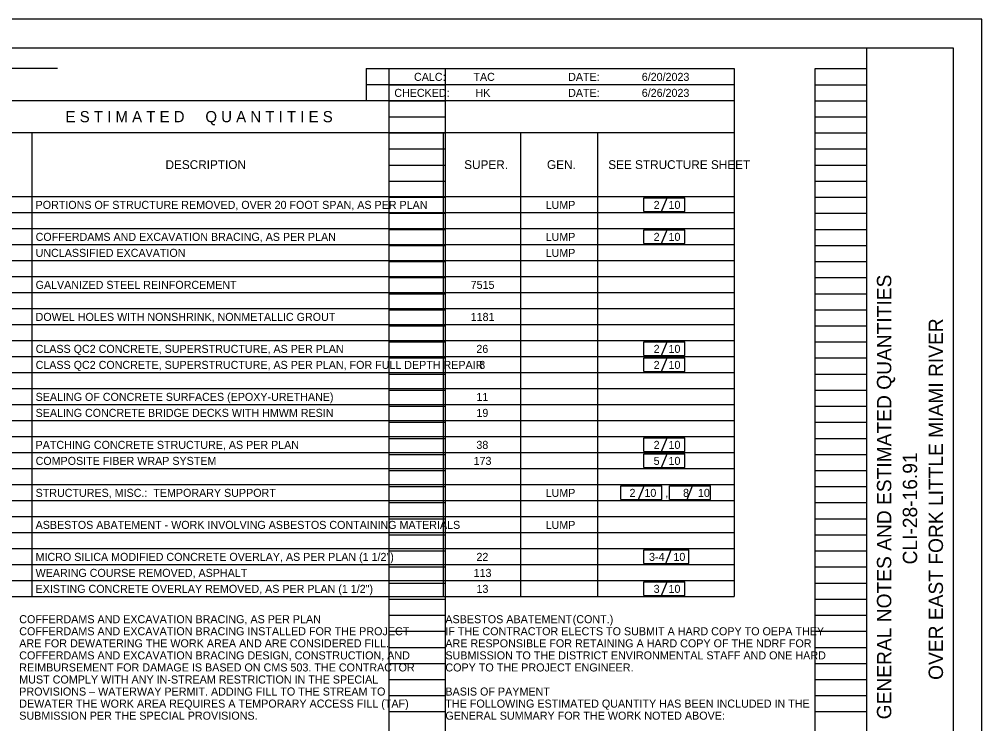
# Model space of a CAD drawing. Extents: x 0 to 34, y 0 to 22.
# Drawn here: x 17.24 to 34, y 9.73 to 22 of the extents above; entities that cross this region are included whole.
import ezdxf

# ---------------------------------------------------------------- set-up
doc = ezdxf.new("R2010")
doc.units = 0
for name, color, linetype in [('BR_P_Gen_Text', 7, 'Continuous'), ('SC_Scratch5', 7, 'Continuous'), ('SH_Border', 7, 'Continuous'), ('SH_Cut_Line', 7, 'Continuous'), ('SH_Data', 7, 'Continuous'), ('SH_Masking', 7, 'Continuous'), ('SH_Text', 7, 'Continuous')]:
    doc.layers.add(name, color=color, linetype=linetype)

msp = doc.modelspace()

# ---------------------------------------------------------------- linework, layer by layer
at = {"layer": 'BR_P_Gen_Text'}
for p, q in [((28.117, 18.888), (28.83, 18.888)), ((28.117, 18.651), (28.117, 18.888)), ((28.426, 18.651), (28.521, 18.888)), ((28.83, 18.651), (28.83, 18.888)), ((28.117, 18.651), (28.83, 18.651)), ((28.117, 18.331), (28.83, 18.331)), ((28.117, 18.093), (28.117, 18.331)), ((28.426, 18.093), (28.521, 18.331)), ((28.83, 18.093), (28.83, 18.331)), ((28.117, 18.093), (28.83, 18.093)), ((28.117, 16.38), (28.83, 16.38)), ((28.117, 16.142), (28.117, 16.38)), ((28.426, 16.142), (28.521, 16.38)), ((28.83, 16.142), (28.83, 16.38)), ((28.117, 16.142), (28.83, 16.142)), ((28.117, 16.101), (28.83, 16.101)), ((28.117, 15.864), (28.117, 16.101)), ((28.426, 15.864), (28.521, 16.101)), ((28.83, 15.864), (28.83, 16.101)), ((28.117, 15.864), (28.83, 15.864)), ((28.117, 14.708), (28.83, 14.708)), ((28.117, 14.47), (28.117, 14.708)), ((28.426, 14.47), (28.521, 14.708)), ((28.83, 14.47), (28.83, 14.708)), ((28.117, 14.47), (28.83, 14.47)), ((28.117, 14.429), (28.83, 14.429)), ((28.117, 14.192), (28.117, 14.429)), ((28.426, 14.192), (28.521, 14.429)), ((28.83, 14.192), (28.83, 14.429)), ((28.117, 14.192), (28.83, 14.192)), ((27.715, 13.872), (28.427, 13.872)), ((27.715, 13.634), (27.715, 13.872)), ((28.024, 13.634), (28.119, 13.872)), ((28.427, 13.634), (28.427, 13.872)), ((28.562, 13.872), (29.274, 13.872)), ((28.562, 13.634), (28.562, 13.872)), ((28.871, 13.634), (28.966, 13.872)), ((29.274, 13.634), (29.274, 13.872)), ((27.715, 13.634), (28.427, 13.634)), ((28.562, 13.634), (29.274, 13.634)), ((28.117, 12.757), (28.901, 12.757)), ((28.117, 12.519), (28.117, 12.757)), ((28.498, 12.519), (28.593, 12.757)), ((28.901, 12.519), (28.901, 12.757)), ((28.117, 12.519), (28.901, 12.519)), ((28.117, 12.199), (28.83, 12.199)), ((28.117, 11.962), (28.117, 12.199)), ((28.426, 11.962), (28.521, 12.199)), ((28.83, 11.962), (28.83, 12.199)), ((28.117, 11.962), (28.83, 11.962))]:
    msp.add_line(p, q, dxfattribs=at)
at = {"layer": 'SC_Scratch5'}
for p, q in [((23.68, 0.98), (23.68, 21.14)), ((23.68, 21.14), (24.66, 21.14)), ((24.66, 0.98), (24.66, 21.14)), ((31.1, 0.98), (31.1, 21.14)), ((31.1, 21.14), (32, 21.14)), ((32, 0.98), (32, 21.14)), ((23.68, 20.86), (24.66, 20.86)), ((31.1, 20.86), (32, 20.86)), ((23.68, 20.58), (24.66, 20.58)), ((31.1, 20.58), (32, 20.58)), ((23.68, 20.3), (24.66, 20.3)), ((31.1, 20.3), (32, 20.3)), ((23.68, 20.02), (24.66, 20.02)), ((31.1, 20.02), (32, 20.02)), ((23.68, 19.74), (24.66, 19.74)), ((31.1, 19.74), (32, 19.74)), ((23.68, 19.46), (24.66, 19.46)), ((31.1, 19.46), (32, 19.46)), ((23.68, 19.18), (24.66, 19.18)), ((31.1, 19.18), (32, 19.18)), ((23.68, 18.9), (24.66, 18.9)), ((31.1, 18.9), (32, 18.9)), ((23.68, 18.62), (24.66, 18.62)), ((31.1, 18.62), (32, 18.62)), ((23.68, 18.34), (24.66, 18.34)), ((31.1, 18.34), (32, 18.34)), ((23.68, 18.06), (24.66, 18.06)), ((31.1, 18.06), (32, 18.06)), ((23.68, 17.78), (24.66, 17.78)), ((31.1, 17.78), (32, 17.78)), ((23.68, 17.5), (24.66, 17.5)), ((31.1, 17.5), (32, 17.5)), ((23.68, 17.22), (24.66, 17.22)), ((31.1, 17.22), (32, 17.22)), ((23.68, 16.94), (24.66, 16.94)), ((31.1, 16.94), (32, 16.94)), ((23.68, 16.66), (24.66, 16.66)), ((31.1, 16.66), (32, 16.66)), ((23.68, 16.38), (24.66, 16.38)), ((31.1, 16.38), (32, 16.38)), ((23.68, 16.1), (24.66, 16.1)), ((31.1, 16.1), (32, 16.1)), ((23.68, 15.82), (24.66, 15.82)), ((31.1, 15.82), (32, 15.82)), ((23.68, 15.54), (24.66, 15.54)), ((31.1, 15.54), (32, 15.54)), ((23.68, 15.26), (24.66, 15.26)), ((31.1, 15.26), (32, 15.26)), ((23.68, 14.98), (24.66, 14.98)), ((31.1, 14.98), (32, 14.98)), ((23.68, 14.7), (24.66, 14.7)), ((31.1, 14.7), (32, 14.7)), ((23.68, 14.42), (24.66, 14.42)), ((31.1, 14.42), (32, 14.42)), ((23.68, 14.14), (24.66, 14.14)), ((31.1, 14.14), (32, 14.14)), ((23.68, 13.86), (24.66, 13.86)), ((31.1, 13.86), (32, 13.86)), ((23.68, 13.58), (24.66, 13.58)), ((31.1, 13.58), (32, 13.58)), ((23.68, 13.3), (24.66, 13.3)), ((31.1, 13.3), (32, 13.3)), ((23.68, 13.02), (24.66, 13.02)), ((31.1, 13.02), (32, 13.02)), ((23.68, 12.74), (24.66, 12.74)), ((31.1, 12.74), (32, 12.74)), ((23.68, 12.46), (24.66, 12.46)), ((31.1, 12.46), (32, 12.46)), ((23.68, 12.18), (24.66, 12.18)), ((31.1, 12.18), (32, 12.18)), ((23.68, 11.9), (24.66, 11.9)), ((31.1, 11.9), (32, 11.9)), ((23.68, 11.62), (24.66, 11.62)), ((31.1, 11.62), (32, 11.62)), ((23.68, 11.34), (24.66, 11.34)), ((31.1, 11.34), (32, 11.34)), ((23.68, 11.06), (24.66, 11.06)), ((31.1, 11.06), (32, 11.06)), ((23.68, 10.78), (24.66, 10.78)), ((31.1, 10.78), (32, 10.78)), ((23.68, 10.5), (24.66, 10.5)), ((31.1, 10.5), (32, 10.5)), ((23.68, 10.22), (24.66, 10.22)), ((31.1, 10.22), (32, 10.22)), ((23.68, 9.94), (24.66, 9.94)), ((31.1, 9.94), (32, 9.94))]:
    msp.add_line(p, q, dxfattribs=at)
at = {"layer": 'SH_Border'}
msp.add_line((32, 0.5), (32, 21.5), dxfattribs=at)
msp.add_lwpolyline([(1.5, 21.5), (33.5, 21.5), (33.5, 0.5), (1.5, 0.5)], close=True, dxfattribs=at)
at = {"layer": 'SH_Cut_Line'}
msp.add_lwpolyline([(0, 0), (34, 0), (34, 22), (0, 22)], close=True, dxfattribs=at)
at = {"layer": 'SH_Masking'}
msp.add_line((17.905, 21.14), (12.085, 21.14), dxfattribs=at)
at = {"layer": 'SH_Text'}
for p, q in [((23.279, 21.14), (29.689, 21.14)), ((23.279, 21.14), (23.279, 20.583)), ((29.689, 21.14), (29.689, 11.943)), ((23.279, 20.861), (29.689, 20.861)), ((10.509, 20.583), (29.689, 20.583)), ((10.509, 20.025), (29.689, 20.025)), ((17.459, 20.025), (17.459, 11.943)), ((24.624, 20.025), (24.624, 11.943)), ((25.968, 20.025), (25.968, 11.943)), ((27.312, 20.025), (27.312, 11.943)), ((10.509, 18.91), (29.689, 18.91)), ((10.509, 18.632), (29.689, 18.632)), ((10.509, 18.353), (29.689, 18.353)), ((10.509, 18.074), (29.689, 18.074)), ((10.509, 17.796), (29.689, 17.796)), ((10.509, 17.517), (29.689, 17.517)), ((10.509, 17.238), (29.689, 17.238)), ((10.509, 16.96), (29.689, 16.96)), ((10.509, 16.681), (29.689, 16.681)), ((10.509, 16.402), (29.689, 16.402)), ((10.509, 16.123), (29.689, 16.123)), ((10.509, 15.845), (29.689, 15.845)), ((10.509, 15.566), (29.689, 15.566)), ((10.509, 15.287), (29.689, 15.287)), ((10.509, 15.009), (29.689, 15.009)), ((10.509, 14.73), (29.689, 14.73)), ((10.509, 14.451), (29.689, 14.451)), ((10.509, 14.173), (29.689, 14.173)), ((10.509, 13.894), (29.689, 13.894)), ((10.509, 13.615), (29.689, 13.615)), ((10.509, 13.337), (29.689, 13.337)), ((10.509, 13.058), (29.689, 13.058)), ((10.509, 12.779), (29.689, 12.779)), ((10.509, 12.5), (29.689, 12.5)), ((10.509, 12.222), (29.689, 12.222)), ((10.509, 11.943), (29.689, 11.943))]:
    msp.add_line(p, q, dxfattribs=at)

# ---------------------------------------------------------------- texts
at = {"layer": 'BR_P_Gen_Text'}
for s, p in [('ASBESTOS ABATEMENT', (24.66, 11.48)), ('  (CONT.)', (26.773, 11.48)), ('IF THE CONTRACTOR ELECTS TO SUBMIT A HARD COPY TO OEPA THEY ', (24.66, 11.27)), ('ARE RESPONSIBLE FOR RETAINING A HARD COPY OF THE NDRF FOR ', (24.66, 11.06)), ('SUBMISSION TO THE DISTRICT ENVIRONMENTAL STAFF AND ONE HARD ', (24.66, 10.85)), ('COPY TO THE PROJECT ENGINEER.   ', (24.66, 10.64)), ('BASIS OF PAYMENT', (24.66, 10.22)), ('THE FOLLOWING ESTIMATED QUANTITY HAS BEEN INCLUDED IN THE ', (24.66, 10.01)), ('GENERAL SUMMARY FOR THE WORK NOTED ABOVE:', (24.66, 9.8))]:
    msp.add_text(s, height=0.14, dxfattribs=at).set_placement(p)
at = {"layer": 'SH_Data'}
for s, p in [('GENERAL NOTES AND ESTIMATED QUANTITIES', (32.425, 9.806)), ('OVER EAST FORK LITTLE MIAMI RIVER', (33.325, 10.493)), ('CLI-28-16.91', (32.875, 12.504))]:
    msp.add_text(s, height=0.25, rotation=90, dxfattribs=at).set_placement(p)
at = {"layer": 'SH_Text'}
for s, height, p in [('CALC:', 0.1393, (24.114, 20.927)), ('TAC', 0.1393, (25.149, 20.927)), ('DATE:', 0.1393, (26.798, 20.927)), ('6/20/2023', 0.1393, (28.08, 20.927)), ('CHECKED:', 0.1393, (23.771, 20.648)), ('HK', 0.1393, (25.185, 20.648)), ('DATE:', 0.1393, (26.798, 20.648)), ('6/26/2023', 0.1393, (28.08, 20.648)), ('E S T I M A T E D     Q U A N T I T I E S', 0.19508, (18.046, 20.206)), ('DESCRIPTION', 0.15328, (19.787, 19.391)), ('SUPER.', 0.1533, (24.988, 19.391)), ('GEN.', 0.1533, (26.429, 19.391)), ('SEE STRUCTURE SHEET', 0.15328, (27.496, 19.391)), ('PORTIONS OF STRUCTURE REMOVED, OVER 20 FOOT SPAN, AS PER PLAN', 0.13935, (17.525, 18.697)), ('LUMP', 0.1393, (26.406, 18.697)), ('2   10', 0.1393, (28.287, 18.697)), ('COFFERDAMS AND EXCAVATION BRACING, AS PER PLAN', 0.13935, (17.525, 18.14)), ('LUMP', 0.1393, (26.406, 18.14)), ('2   10', 0.1393, (28.287, 18.14)), ('UNCLASSIFIED EXCAVATION', 0.13935, (17.525, 17.861)), ('LUMP', 0.1393, (26.406, 17.861)), ('GALVANIZED STEEL REINFORCEMENT', 0.13935, (17.525, 17.304)), ('7515', 0.1393, (25.101, 17.304)), ('DOWEL HOLES WITH NONSHRINK, NONMETALLIC GROUT', 0.13935, (17.525, 16.746)), ('1181', 0.1393, (25.101, 16.746)), ('CLASS QC2 CONCRETE, SUPERSTRUCTURE, AS PER PLAN', 0.13935, (17.525, 16.189)), ('26', 0.1393, (25.2, 16.189)), ('2   10', 0.1393, (28.287, 16.189)), ('CLASS QC2 CONCRETE, SUPERSTRUCTURE, AS PER PLAN, FOR FULL DEPTH REPAIR', 0.13935, (17.525, 15.91)), ('8', 0.139, (25.25, 15.91)), ('2   10', 0.1393, (28.287, 15.91)), ('SEALING OF CONCRETE SURFACES (EPOXY-URETHANE)', 0.13935, (17.525, 15.353)), ('11', 0.1393, (25.201, 15.353)), ('SEALING CONCRETE BRIDGE DECKS WITH HMWM RESIN', 0.13935, (17.525, 15.074)), ('19', 0.1393, (25.201, 15.074)), ('PATCHING CONCRETE STRUCTURE, AS PER PLAN', 0.13935, (17.525, 14.517)), ('38', 0.1393, (25.2, 14.517)), ('2   10', 0.1393, (28.287, 14.517)), ('COMPOSITE FIBER WRAP SYSTEM', 0.13935, (17.525, 14.238)), ('173', 0.1393, (25.152, 14.238)), ('5   10', 0.1393, (28.287, 14.238)), ('STRUCTURES, MISC.:  TEMPORARY SUPPORT', 0.13935, (17.525, 13.681)), ('LUMP', 0.1393, (26.406, 13.681)), ('2   10   ,     8   10', 0.13935, (27.867, 13.681)), ('ASBESTOS ABATEMENT - WORK INVOLVING ASBESTOS CONTAINING MATERIALS', 0.13935, (17.525, 13.123)), ('LUMP', 0.1393, (26.406, 13.123)), ('MICRO SILICA MODIFIED CONCRETE OVERLAY, AS PER PLAN (1 1/2")', 0.13935, (17.525, 12.566)), ('22', 0.1393, (25.201, 12.566)), ('3-4   10', 0.1393, (28.207, 12.566)), ('WEARING COURSE REMOVED, ASPHALT', 0.13935, (17.525, 12.287)), ('113', 0.1393, (25.152, 12.287)), ('EXISTING CONCRETE OVERLAY REMOVED, AS PER PLAN (1 1/2")', 0.13935, (17.525, 12.009)), ('13', 0.1393, (25.202, 12.009)), ('3   10', 0.1393, (28.287, 12.009)), ('COFFERDAMS AND EXCAVATION BRACING, AS PER PLAN', 0.14, (17.24, 11.48)), ('COFFERDAMS AND EXCAVATION BRACING INSTALLED FOR THE PROJECT ', 0.14, (17.24, 11.27)), ('ARE FOR DEWATERING THE WORK AREA AND ARE CONSIDERED FILL. ', 0.14, (17.24, 11.06)), ('COFFERDAMS AND EXCAVATION BRACING DESIGN, CONSTRUCTION, AND ', 0.14, (17.24, 10.85)), ('REIMBURSEMENT FOR DAMAGE IS BASED ON CMS 503. THE CONTRACTOR ', 0.14, (17.24, 10.64)), ('MUST COMPLY WITH ANY IN-STREAM RESTRICTION IN THE SPECIAL ', 0.14, (17.24, 10.43)), ('PROVISIONS – WATERWAY PERMIT. ADDING FILL TO THE STREAM TO ', 0.14, (17.24, 10.22)), ('DEWATER THE WORK AREA REQUIRES A TEMPORARY ACCESS FILL (TAF) ', 0.14, (17.24, 10.01)), ('SUBMISSION PER THE SPECIAL PROVISIONS.', 0.14, (17.24, 9.8))]:
    msp.add_text(s, height=height, dxfattribs=at).set_placement(p)

doc.saveas('drawing.dxf')
